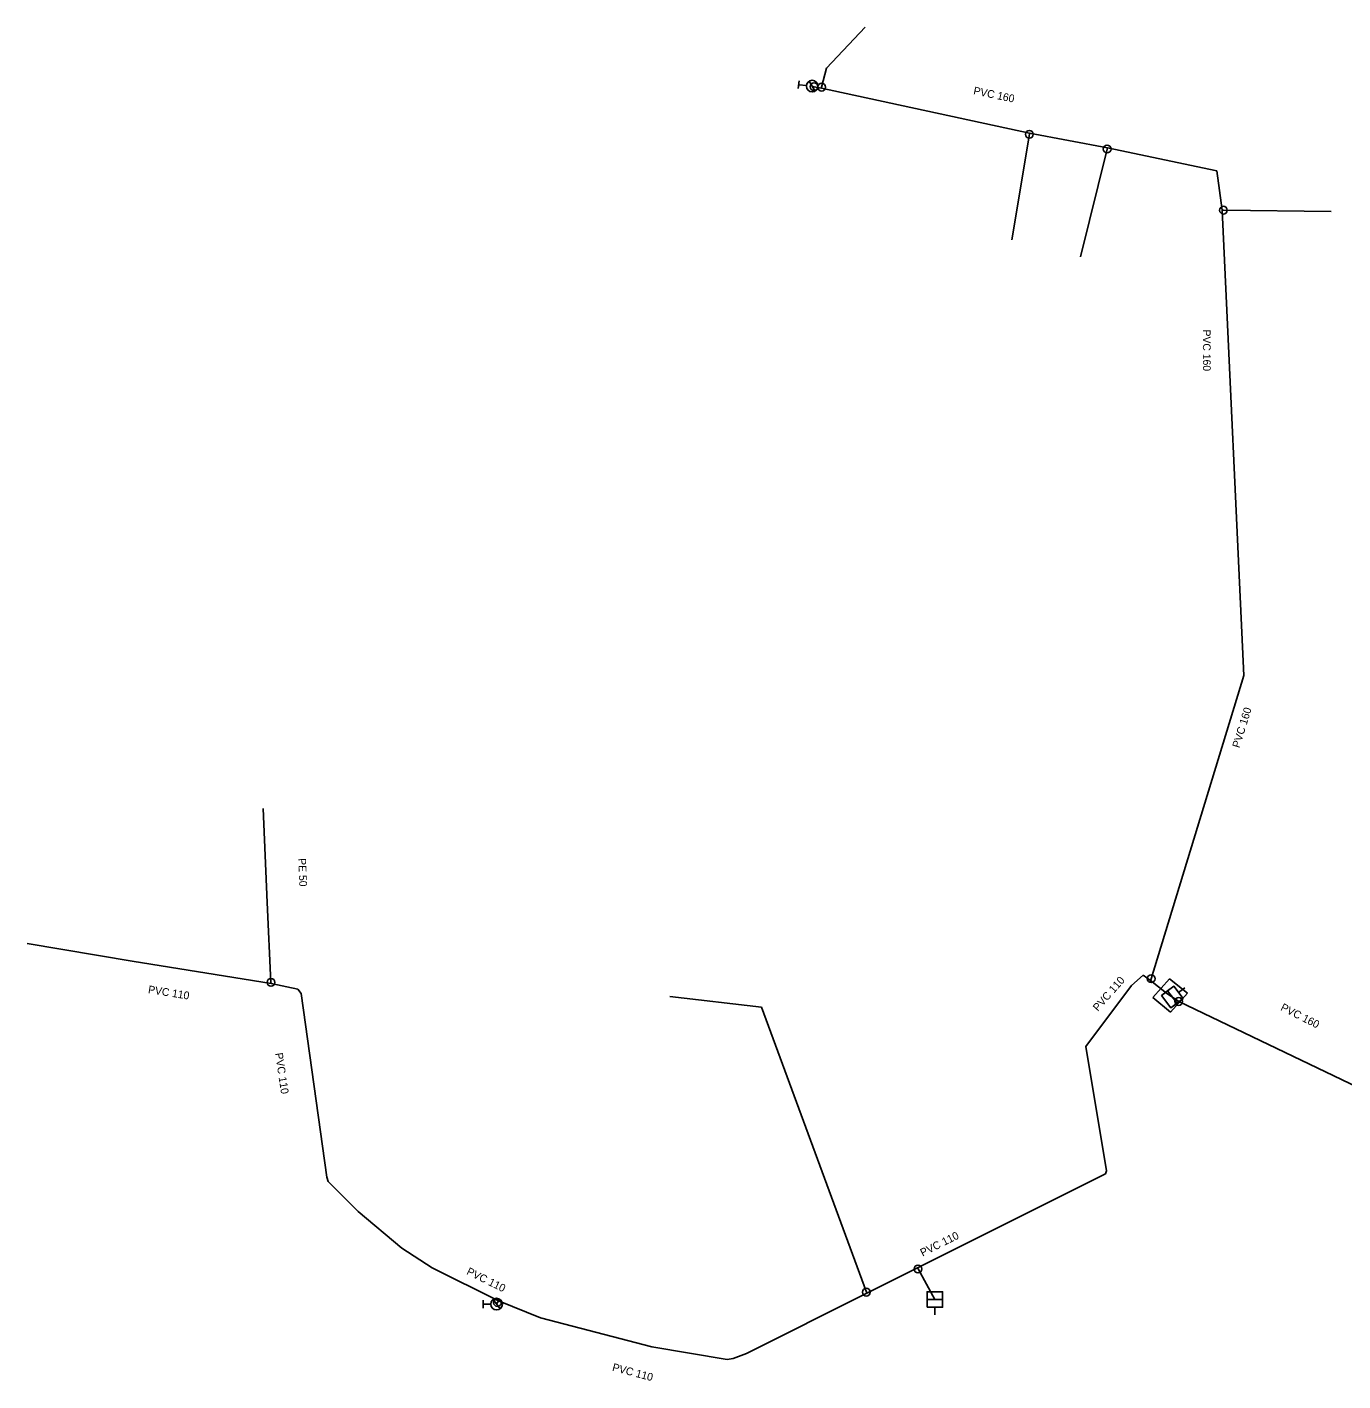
# Model space of a CAD drawing. Extents: x -643485 to -643037, y -1068047 to -1067198.
# Drawn here: x -643485.2 to -643315.6, y -1068030.3 to -1067855.9 of the extents above; entities that cross this region are included whole.
import ezdxf

# ---------------------------------------------------------------- set-up
doc = ezdxf.new("R2010")
doc.units = 0
doc.layers.add('Level 0', color=7, linetype='Continuous')

msp = doc.modelspace()

# ---------------------------------------------------------------- linework, layer by layer
at = {"layer": 'Level 0'}
for p, q in [((-643382.2, -1067861.15), (-643377.21, -1067855.85)), ((-643382.83, -1067863.59), (-643382.2, -1067861.15)), ((-643385.84, -1067863.77), (-643385.74, -1067862.77)), ((-643384.8, -1067863.38), (-643385.79, -1067863.27)), ((-643383.65, -1067864.09), (-643384.45, -1067862.82)), ((-643383.82, -1067863.53), (-643384.05, -1067863.46)), ((-643382.85, -1067863.74), (-643383.82, -1067863.53)), ((-643382.85, -1067863.74), (-643382.83, -1067863.59)), ((-643356.03, -1067869.53), (-643382.85, -1067863.74)), ((-643356.05, -1067869.66), (-643358.33, -1067883.24)), ((-643356.03, -1067869.53), (-643356.05, -1067869.66)), ((-643346, -1067871.41), (-643356.03, -1067869.53)), ((-643346.03, -1067871.56), (-643349.45, -1067885.43)), ((-643345.99, -1067871.41), (-643346.03, -1067871.56)), ((-643331.88, -1067874.38), (-643346, -1067871.41)), ((-643331.19, -1067879.44), (-643331.88, -1067874.38)), ((-643331.19, -1067879.44), (-643331.04, -1067879.44)), ((-643328.39, -1067939.39), (-643331.19, -1067879.44)), ((-643331.04, -1067879.44), (-643317.15, -1067879.63)), ((-643340.35, -1067978.45), (-643328.39, -1067939.39)), ((-643454.29, -1067968.63), (-643454.8, -1067956.52)), ((-643453.81, -1067978.92), (-643454.29, -1067968.63)), ((-643485.25, -1067973.91), (-643471.72, -1067976.18)), ((-643471.72, -1067976.18), (-643453.8, -1067979.06)), ((-643342.9, -1067979.34), (-643341.38, -1067977.97)), ((-643341.38, -1067977.97), (-643340.43, -1067978.69)), ((-643340.43, -1067978.69), (-643340.35, -1067978.45)), ((-643338.38, -1067980.31), (-643340.43, -1067978.69)), ((-643337.97, -1067978.45), (-643340.14, -1067980.85)), ((-643335.68, -1067980.3), (-643337.97, -1067978.45)), ((-643453.8, -1067979.06), (-643453.81, -1067978.92)), ((-643453.8, -1067979.06), (-643450.33, -1067979.79)), ((-643450.33, -1067979.79), (-643449.92, -1067980.35)), ((-643449.92, -1067980.35), (-643446.61, -1068004.03)), ((-643348.78, -1067987.16), (-643342.9, -1067979.34)), ((-643337.43, -1067979.42), (-643339.02, -1067980.63)), ((-643336.8, -1067981.38), (-643338.38, -1067980.31)), ((-643337.85, -1067982.74), (-643335.68, -1067980.3)), ((-643336.22, -1067981.01), (-643337.43, -1067979.42)), ((-643336.03, -1067979.61), (-643336.83, -1067980.21)), ((-643390.58, -1067982.1), (-643402.4, -1067980.75)), ((-643377.06, -1068018.83), (-643390.58, -1067982.1)), ((-643340.14, -1067980.85), (-643337.85, -1067982.74)), ((-643339.02, -1067980.63), (-643337.81, -1067982.22)), ((-643337.81, -1067982.22), (-643336.22, -1067981.01)), ((-643313.68, -1067992.48), (-643336.8, -1067981.38)), ((-643346.1, -1068003.2), (-643348.78, -1067987.16)), ((-643346.23, -1068003.6), (-643346.1, -1068003.2)), ((-643446.61, -1068004.03), (-643446.44, -1068004.56)), ((-643446.44, -1068004.56), (-643442.56, -1068008.44)), ((-643370.47, -1068015.71), (-643346.23, -1068003.6)), ((-643442.56, -1068008.44), (-643436.94, -1068013.15)), ((-643436.94, -1068013.15), (-643433.02, -1068015.69)), ((-643433.02, -1068015.69), (-643424.5, -1068019.94)), ((-643377.01, -1068018.97), (-643370.47, -1068015.71)), ((-643370.47, -1068015.71), (-643370.4, -1068015.84)), ((-643370.4, -1068015.84), (-643368.23, -1068019.77)), ((-643377.01, -1068018.97), (-643377.06, -1068018.83)), ((-643426.48, -1068020.87), (-643426.48, -1068019.87)), ((-643425.48, -1068020.37), (-643426.48, -1068020.37)), ((-643424.27, -1068020.96), (-643425.19, -1068019.78)), ((-643424.62, -1068020.17), (-643424.73, -1068020.37)), ((-643424.5, -1068019.94), (-643424.62, -1068020.17)), ((-643424.5, -1068019.94), (-643419.06, -1068022.14)), ((-643392.51, -1068026.71), (-643377.01, -1068018.97)), ((-643419.06, -1068022.14), (-643404.72, -1068025.85)), ((-643368.23, -1068021.77), (-643368.23, -1068020.77)), ((-643404.72, -1068025.85), (-643395, -1068027.5)), ((-643395, -1068027.5), (-643394.23, -1068027.39)), ((-643394.23, -1068027.39), (-643392.51, -1068026.71))]:
    msp.add_line(p, q, dxfattribs=at)
for points in [[(-643337.01, -1067981.61), (-643337.81, -1067982.22), (-643339.02, -1067980.63), (-643338.23, -1067980.03)], [(-643369.23, -1068019.77), (-643369.23, -1068018.77), (-643367.23, -1068018.77), (-643367.23, -1068019.77)]]:
    msp.add_lwpolyline(points, dxfattribs=at)
for points in [[(-643336.22, -1067981.01), (-643337.43, -1067979.42), (-643338.23, -1067980.03), (-643337.01, -1067981.61)], [(-643369.23, -1068020.77), (-643367.23, -1068020.77), (-643367.23, -1068019.77), (-643369.23, -1068019.77)]]:
    msp.add_lwpolyline(points, close=True, dxfattribs=at)
for centre, radius in [((-643384.05, -1067863.46), 0.75), ((-643383.82, -1067863.53), 0.5), ((-643382.83, -1067863.59), 0.5), ((-643356.05, -1067869.66), 0.5), ((-643346.03, -1067871.56), 0.5), ((-643331.04, -1067879.44), 0.5), ((-643453.81, -1067978.92), 0.5), ((-643340.35, -1067978.45), 0.5), ((-643336.8, -1067981.38), 0.5), ((-643370.4, -1068015.84), 0.5), ((-643377.06, -1068018.83), 0.5), ((-643424.73, -1068020.37), 0.75), ((-643424.62, -1068020.17), 0.5)]:
    msp.add_circle(centre, radius, dxfattribs=at)

# ---------------------------------------------------------------- texts
for s, rotation, p in [('PVC 160', 348.157, (-643363.33, -1067864.49)), ('PVC 160', 270.188, (-643333.69, -1067894.82)), ('PVC 160', 72.72, (-643328.98, -1067948.79)), ('PE 50', 272.412, (-643450.3, -1067962.95)), ('PVC 110', 48.609, (-643347.22, -1067982.72)), ('PVC 110', 350.87, (-643469.7, -1067980.29)), ('PVC 160', 333.119, (-643323.76, -1067982.46)), ('PVC 110', 278.597, (-643453.29, -1067988.06)), ('PVC 110', 26.535, (-643369.82, -1068014.26)), ('PVC 110', 333.611, (-643428.69, -1068016.48)), ('PVC 110', 345.118, (-643409.89, -1068028.93))]:
    msp.add_text(s, height=1, rotation=rotation, dxfattribs=at).set_placement(p)

doc.saveas('drawing.dxf')
